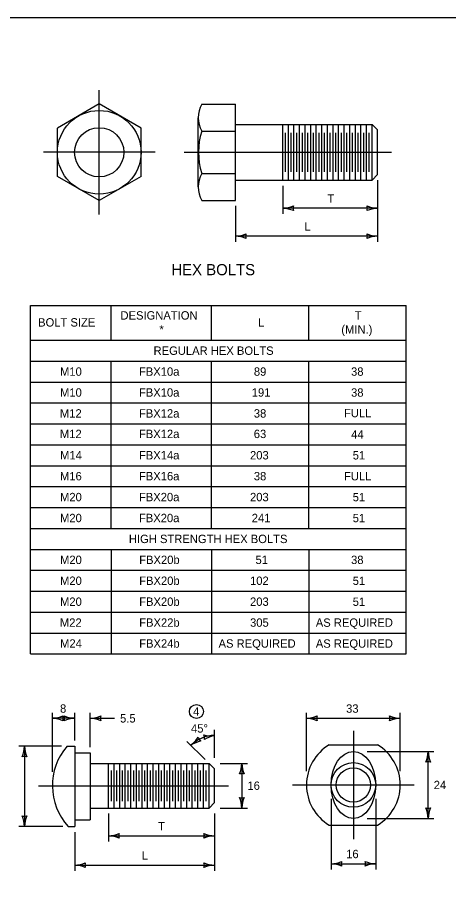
# Model space of a CAD drawing. Extents: x 49991.4 to 50021, y 49987.6 to 50011.4.
# Drawn here: x 50008.65 to 50011.74, y 49992.68 to 49999 of the extents above; entities that cross this region are included whole.
import ezdxf

# ---------------------------------------------------------------- set-up
doc = ezdxf.new("R2010")
doc.units = 0
for name, color, linetype in [('Level 1', 7, 'Continuous'), ('Level 2', 7, 'Continuous'), ('Level 3', 7, 'Continuous'), ('Level 4', 7, 'Continuous'), ('Level 5', 7, 'Continuous')]:
    doc.layers.add(name, color=color, linetype=linetype)

msp = doc.modelspace()

# ---------------------------------------------------------------- linework, layer by layer
at = {"layer": 'Level 1'}
for p, q in [((50009.2322, 49998.3799), (50008.9322, 49998.2067)), ((50009.5322, 49998.2067), (50009.2322, 49998.3799)), ((50009.9665, 49998.3782), (50010.2082, 49998.3782)), ((50010.2082, 49997.6887), (50010.2082, 49998.3782)), ((50009.9412, 49997.7862), (50009.9412, 49998.2808)), ((50008.9322, 49997.8602), (50008.9322, 49998.2067)), ((50009.5322, 49997.8602), (50009.5322, 49998.2067)), ((50010.2082, 49998.2335), (50011.1882, 49998.2335)), ((50010.5482, 49997.8335), (50010.5482, 49998.2335)), ((50010.5882, 49997.8335), (50010.5882, 49998.2335)), ((50010.6282, 49997.8335), (50010.6282, 49998.2335)), ((50010.6682, 49997.8335), (50010.6682, 49998.2335)), ((50010.7082, 49997.8335), (50010.7082, 49998.2335)), ((50010.7482, 49997.8335), (50010.7482, 49998.2335)), ((50010.7882, 49997.8335), (50010.7882, 49998.2335)), ((50010.8282, 49997.8335), (50010.8282, 49998.2335)), ((50010.8682, 49997.8335), (50010.8682, 49998.2335)), ((50010.9082, 49997.8335), (50010.9082, 49998.2335)), ((50010.9482, 49997.8335), (50010.9482, 49998.2335)), ((50010.9882, 49997.8335), (50010.9882, 49998.2335)), ((50011.0282, 49997.8335), (50011.0282, 49998.2335)), ((50011.0682, 49997.8335), (50011.0682, 49998.2335)), ((50011.1082, 49997.8335), (50011.1082, 49998.2335)), ((50011.1482, 49997.8335), (50011.1482, 49998.2335)), ((50011.1882, 49997.8335), (50011.1882, 49998.2335)), ((50011.1882, 49998.2335), (50011.2282, 49998.1935)), ((50009.9665, 49998.1852), (50010.2082, 49998.1852)), ((50010.5682, 49997.8935), (50010.5682, 49998.1735)), ((50010.6082, 49997.8935), (50010.6082, 49998.1735)), ((50010.6482, 49997.8935), (50010.6482, 49998.1735)), ((50010.6882, 49997.8935), (50010.6882, 49998.1735)), ((50010.7282, 49997.8935), (50010.7282, 49998.1735)), ((50010.7682, 49997.8935), (50010.7682, 49998.1735)), ((50010.8082, 49997.8935), (50010.8082, 49998.1735)), ((50010.8482, 49997.8935), (50010.8482, 49998.1735)), ((50010.8882, 49997.8935), (50010.8882, 49998.1735)), ((50010.9282, 49997.8935), (50010.9282, 49998.1735)), ((50010.9682, 49997.8935), (50010.9682, 49998.1735)), ((50011.0082, 49997.8935), (50011.0082, 49998.1735)), ((50011.0482, 49997.8935), (50011.0482, 49998.1735)), ((50011.0882, 49997.8935), (50011.0882, 49998.1735)), ((50011.1282, 49997.8935), (50011.1282, 49998.1735)), ((50011.1682, 49997.8935), (50011.1682, 49998.1735)), ((50011.2282, 49997.8735), (50011.2282, 49998.1935)), ((50009.2322, 49997.687), (50008.9322, 49997.8602)), ((50009.5322, 49997.8602), (50009.2322, 49997.687)), ((50009.9665, 49997.8817), (50010.2082, 49997.8817)), ((50010.2082, 49997.8335), (50011.1882, 49997.8335)), ((50011.1882, 49997.8335), (50011.2282, 49997.8735)), ((50009.9665, 49997.6887), (50010.2082, 49997.6887)), ((50010.881, 49993.7844), (50011.2271, 49993.7844)), ((50009.0016, 49993.7743), (50009.0562, 49993.7743)), ((50009.0562, 49993.7743), (50009.0562, 49993.1983)), ((50009.0562, 49993.7263), (50009.1682, 49993.7263)), ((50009.1682, 49993.7263), (50009.1682, 49993.2463)), ((50009.1682, 49993.6512), (50010.0192, 49993.6512)), ((50009.2992, 49993.3312), (50009.2992, 49993.6512)), ((50009.3192, 49993.3812), (50009.3192, 49993.6012)), ((50009.3392, 49993.3312), (50009.3392, 49993.6512)), ((50009.3592, 49993.3812), (50009.3592, 49993.6012)), ((50009.3792, 49993.3312), (50009.3792, 49993.6512)), ((50009.3992, 49993.3812), (50009.3992, 49993.6012)), ((50009.4192, 49993.3312), (50009.4192, 49993.6512)), ((50009.4392, 49993.3812), (50009.4392, 49993.6012)), ((50009.4592, 49993.3312), (50009.4592, 49993.6512)), ((50009.4792, 49993.3812), (50009.4792, 49993.6012)), ((50009.4992, 49993.3312), (50009.4992, 49993.6512)), ((50009.5192, 49993.3812), (50009.5192, 49993.6012)), ((50009.5392, 49993.3312), (50009.5392, 49993.6512)), ((50009.5592, 49993.3812), (50009.5592, 49993.6012)), ((50009.5792, 49993.3312), (50009.5792, 49993.6512)), ((50009.5992, 49993.3812), (50009.5992, 49993.6012)), ((50009.6192, 49993.3312), (50009.6192, 49993.6512)), ((50009.6392, 49993.3812), (50009.6392, 49993.6012)), ((50009.6592, 49993.3312), (50009.6592, 49993.6512)), ((50009.6792, 49993.3812), (50009.6792, 49993.6012)), ((50009.6992, 49993.3312), (50009.6992, 49993.6512)), ((50009.7192, 49993.3812), (50009.7192, 49993.6012)), ((50009.7392, 49993.3312), (50009.7392, 49993.6512)), ((50009.7592, 49993.3812), (50009.7592, 49993.6012)), ((50009.7792, 49993.3312), (50009.7792, 49993.6512)), ((50009.7992, 49993.3812), (50009.7992, 49993.6012)), ((50009.8192, 49993.3312), (50009.8192, 49993.6512)), ((50009.8392, 49993.3812), (50009.8392, 49993.6012)), ((50009.8592, 49993.3312), (50009.8592, 49993.6512)), ((50009.8792, 49993.3812), (50009.8792, 49993.6012)), ((50009.8992, 49993.3312), (50009.8992, 49993.6512)), ((50009.9192, 49993.3812), (50009.9192, 49993.6012)), ((50009.9392, 49993.3312), (50009.9392, 49993.6512)), ((50009.9592, 49993.3812), (50009.9592, 49993.6012)), ((50009.9792, 49993.3312), (50009.9792, 49993.6512)), ((50009.9992, 49993.3812), (50009.9992, 49993.6012)), ((50010.0192, 49993.3312), (50010.0192, 49993.6512)), ((50010.0192, 49993.6512), (50010.0592, 49993.6112)), ((50010.0592, 49993.3712), (50010.0592, 49993.6112)), ((50010.0192, 49993.3312), (50010.0592, 49993.3712)), ((50009.1682, 49993.3312), (50010.0192, 49993.3312)), ((50009.0562, 49993.2463), (50009.1682, 49993.2463)), ((50009.0104, 49993.1983), (50009.0562, 49993.1983)), ((50010.881, 49993.2084), (50011.2271, 49993.2084))]:
    msp.add_line(p, q, dxfattribs=at)
msp.add_lwpolyline([(49999.3835, 49998.9992), (50016.7501, 49998.9992), (50016.7501, 49987.7988), (49999.3835, 49987.7988)], close=True, dxfattribs=at)
for centre, radius in [((50009.2322, 49998.0335), 0.3), ((50011.0541, 49993.4964), 0.16), ((50011.0541, 49993.4964), 0.1225)]:
    msp.add_circle(centre, radius, dxfattribs=at)
for centre, radius, start, end in [((50010.1375, 49998.2817), 0.1963, 150.55282, 209.44718), ((50010.4667, 49998.0335), 0.5227, 163.12246, 196.87789), ((50010.1375, 49997.7852), 0.1963, 150.55289, 209.4483), ((50011.0541, 49993.4964), 0.336, 121.00272, 238.99728), ((50011.0541, 49993.4964), 0.336, 301.00272, 58.99728), ((50009.329, 49993.4912), 0.4328, 139.14882, 222.59192)]:
    msp.add_arc(centre, radius, start, end, dxfattribs=at)
msp.add_ellipse((50011.0541, 49993.4964), major_axis=(0, 0.24), ratio=0.666667, dxfattribs=at)
at = {"layer": 'Level 2'}
for p, q in [((50008.7404, 49996.936), (50011.4317, 49996.936)), ((50008.7404, 49994.436), (50008.7404, 49996.936)), ((50009.317, 49996.686), (50009.317, 49996.936)), ((50010.037, 49996.686), (50010.037, 49996.936)), ((50010.7344, 49996.686), (50010.7344, 49996.936)), ((50011.4317, 49994.436), (50011.4317, 49996.936)), ((50008.7404, 49996.686), (50011.4317, 49996.686)), ((50008.7404, 49996.536), (50011.4317, 49996.536)), ((50009.317, 49995.336), (50009.317, 49996.536)), ((50010.037, 49995.336), (50010.037, 49996.536)), ((50010.7344, 49995.336), (50010.7344, 49996.536)), ((50008.7404, 49996.386), (50011.4317, 49996.386)), ((50008.7404, 49996.236), (50011.4317, 49996.236)), ((50008.7404, 49996.086), (50011.4317, 49996.086)), ((50008.7404, 49995.936), (50011.4317, 49995.936)), ((50008.7404, 49995.786), (50011.4317, 49995.786)), ((50008.7404, 49995.636), (50011.4317, 49995.636)), ((50008.7404, 49995.486), (50011.4317, 49995.486)), ((50008.7404, 49995.336), (50011.4317, 49995.336)), ((50008.7404, 49995.186), (50011.4317, 49995.186)), ((50009.317, 49995.186), (50009.317, 49994.436)), ((50010.037, 49995.186), (50010.037, 49994.436)), ((50010.7344, 49995.186), (50010.7344, 49994.436)), ((50008.7404, 49995.036), (50011.4317, 49995.036)), ((50008.7404, 49994.886), (50011.4317, 49994.886)), ((50008.7404, 49994.736), (50011.4317, 49994.736)), ((50008.7404, 49994.586), (50011.4317, 49994.586)), ((50008.7404, 49994.436), (50011.4317, 49994.436))]:
    msp.add_line(p, q, dxfattribs=at)
msp.add_circle((50009.9289, 49994.0231), 0.05, dxfattribs=at)
at = {"layer": 'Level 3'}
for p, q in [((50011.2282, 49997.8335), (50011.2282, 49997.3919)), ((50010.5482, 49997.7935), (50010.5482, 49997.5919)), ((50010.2082, 49997.6487), (50010.2082, 49997.3919)), ((50011.2282, 49997.6319), (50010.5482, 49997.6319)), ((50011.2282, 49997.4319), (50010.2082, 49997.4319)), ((50008.8962, 49993.5912), (50008.8962, 49994.0143)), ((50009.0562, 49993.9743), (50008.8962, 49993.9743)), ((50009.0562, 49993.8143), (50009.0562, 49994.0143)), ((50009.1682, 49993.7663), (50009.1682, 49994.0143)), ((50009.1682, 49993.9743), (50009.3416, 49993.9743)), ((50010.7181, 49993.5964), (50010.7181, 49994.0143)), ((50010.7181, 49993.9743), (50011.3901, 49993.9743)), ((50011.3901, 49993.5964), (50011.3901, 49994.0143)), ((50010.0592, 49993.6912), (50010.0592, 49993.8912)), ((50009.991, 49993.6795), (50009.8612, 49993.8092)), ((50008.9616, 49993.7743), (50008.6562, 49993.7743)), ((50008.6962, 49993.7743), (50008.6962, 49993.1983)), ((50011.1541, 49993.7364), (50011.6301, 49993.7364)), ((50011.5901, 49993.2564), (50011.5901, 49993.7364)), ((50010.0992, 49993.6512), (50010.2948, 49993.6512)), ((50010.2548, 49993.6512), (50010.2548, 49993.3312)), ((50010.8941, 49993.3964), (50010.8941, 49992.8913)), ((50011.2141, 49993.3964), (50011.2141, 49992.8913)), ((50009.2992, 49993.2912), (50009.2992, 49993.0912)), ((50010.0592, 49993.2912), (50010.0592, 49992.8812)), ((50010.0992, 49993.3312), (50010.2948, 49993.3312)), ((50011.1541, 49993.2564), (50011.6301, 49993.2564)), ((50008.9704, 49993.1983), (50008.6562, 49993.1983)), ((50009.0562, 49993.1583), (50009.0562, 49992.8812)), ((50009.2992, 49993.1312), (50010.0592, 49993.1312)), ((50009.0562, 49992.9212), (50010.0592, 49992.9212)), ((50010.8941, 49992.9313), (50011.2141, 49992.9313))]:
    msp.add_line(p, q, dxfattribs=at)
for centre, radius, start, end in [((50010.5367, 49997.8646), 0.233, 272.82731, 292.07716), ((50010.6764, 49997.6319), 0.0548, 162.13882, 197.86118), ((50011.2373, 49997.854), 0.2223, 247.45601, 267.63952), ((50011.1, 49997.6319), 0.0548, 342.13882, 17.86118), ((50010.539, 49997.4097), 0.2223, 67.45601, 87.63952), ((50011.2397, 49997.3992), 0.233, 92.82731, 112.07716), ((50010.1967, 49997.6646), 0.233, 272.82731, 292.07716), ((50010.3364, 49997.4319), 0.0548, 162.13882, 197.86118), ((50011.2373, 49997.654), 0.2223, 247.45601, 267.63952), ((50011.1, 49997.4319), 0.0548, 342.13882, 17.86118), ((50010.199, 49997.2097), 0.2223, 67.45601, 87.63952), ((50011.2397, 49997.1992), 0.233, 92.82731, 112.07716), ((50008.8847, 49994.207), 0.233, 272.82731, 292.07716), ((50008.887, 49993.7522), 0.2223, 67.45601, 87.63952), ((50009.0244, 49993.9743), 0.0548, 162.13882, 197.86118), ((50009.0654, 49994.1964), 0.2223, 247.45601, 267.63952), ((50008.928, 49993.9743), 0.0548, 342.13882, 17.86118), ((50009.0677, 49993.7416), 0.233, 92.82731, 112.07716), ((50009.1567, 49994.207), 0.233, 272.82731, 292.07716), ((50009.159, 49993.7522), 0.2223, 67.45601, 87.63952), ((50009.2964, 49993.9743), 0.0548, 162.13882, 197.86118), ((50010.7089, 49994.1964), 0.2223, 272.36047, 292.54398), ((50010.7066, 49993.7416), 0.233, 67.92283, 87.17268), ((50010.8463, 49993.9743), 0.0548, 162.13881, 197.86118), ((50011.2619, 49993.9743), 0.0548, 342.13881, 17.86118), ((50011.4016, 49994.207), 0.233, 247.92283, 267.17268), ((50011.3992, 49993.7522), 0.2223, 92.36047, 112.54398), ((50010.0592, 49993.6112), 0.24, 90, 135.00008), ((50010.0324, 49994.0719), 0.2223, 256.74849, 276.932), ((50009.9327, 49993.8305), 0.0548, 351.4313, 27.15366), ((50010.1082, 49993.6234), 0.233, 102.11979, 121.36964), ((50009.7438, 49993.9627), 0.233, 308.71738, 327.96723), ((50010.0123, 49993.5956), 0.2223, 103.34608, 123.52958), ((50009.9934, 49993.8561), 0.0548, 198.02888, 233.75125), ((50008.4741, 49993.7835), 0.2223, 337.45596, 357.63947), ((50008.9289, 49993.7858), 0.233, 182.82726, 202.07711), ((50011.3679, 49993.7456), 0.2223, 337.45596, 357.63947), ((50011.8228, 49993.7479), 0.233, 182.82726, 202.07711), ((50008.6962, 49993.6461), 0.0548, 72.13877, 107.86113), ((50011.5901, 49993.6082), 0.0548, 72.13877, 107.86113), ((50010.0326, 49993.6604), 0.2223, 337.45596, 357.63947), ((50010.4875, 49993.6627), 0.233, 182.82726, 202.07711), ((50010.2548, 49993.523), 0.0548, 72.13877, 107.86113), ((50010.2548, 49993.4594), 0.0548, 252.13877, 287.86113), ((50010.0221, 49993.3197), 0.233, 2.82726, 22.07711), ((50010.4769, 49993.3221), 0.2223, 157.45596, 177.63947), ((50008.6962, 49993.3265), 0.0548, 252.13877, 287.86113), ((50008.4635, 49993.1868), 0.233, 2.82726, 22.07711), ((50008.9183, 49993.1891), 0.2223, 157.45596, 177.63947), ((50011.5901, 49993.3846), 0.0548, 252.13877, 287.86113), ((50011.3574, 49993.2449), 0.233, 2.82726, 22.07711), ((50011.8122, 49993.2473), 0.2223, 157.45596, 177.63947), ((50009.2877, 49993.3639), 0.233, 272.82731, 292.07716), ((50009.4275, 49993.1312), 0.0548, 162.13882, 197.86118), ((50010.0684, 49993.3534), 0.2223, 247.45601, 267.63952), ((50009.931, 49993.1312), 0.0548, 342.13882, 17.86118), ((50009.2901, 49992.9091), 0.2223, 67.45601, 87.63952), ((50010.0707, 49992.8985), 0.233, 92.82731, 112.07716), ((50009.0447, 49993.1539), 0.233, 272.82731, 292.07716), ((50009.047, 49992.6991), 0.2223, 67.45601, 87.63952), ((50009.1844, 49992.9212), 0.0548, 162.13882, 197.86118), ((50010.0684, 49993.1434), 0.2223, 247.45601, 267.63952), ((50009.931, 49992.9212), 0.0548, 342.13882, 17.86118), ((50010.0707, 49992.6885), 0.233, 92.82731, 112.07716), ((50010.8849, 49993.1535), 0.2223, 272.36047, 292.54398), ((50010.8826, 49992.6986), 0.233, 67.92283, 87.17268), ((50011.0223, 49992.9313), 0.0548, 162.13881, 197.86118), ((50011.0859, 49992.9313), 0.0548, 342.13881, 17.86118), ((50011.2256, 49993.1641), 0.233, 247.92283, 267.17268), ((50011.2232, 49992.7092), 0.2223, 92.36047, 112.54398)]:
    msp.add_arc(centre, radius, start, end, dxfattribs=at)
at = {"layer": 'Level 4'}
msp.add_circle((50009.2322, 49998.0335), 0.1765, dxfattribs=at)
at = {"layer": 'Level 5'}
for p, q in [((50009.2322, 49997.587), (50009.2322, 49998.4799)), ((50009.6322, 49998.0335), (50008.8322, 49998.0335)), ((50009.8412, 49998.0335), (50011.3282, 49998.0335)), ((50011.0541, 49993.8844), (50011.0541, 49993.1084)), ((50008.7962, 49993.4912), (50010.1592, 49993.4912)), ((50010.6181, 49993.4964), (50011.4901, 49993.4964))]:
    msp.add_line(p, q, dxfattribs=at)

# ---------------------------------------------------------------- texts
at = {"layer": 'Level 2'}
for s, height, p in [('T', 0.06, (50010.8685, 49997.6719)), ('L', 0.06, (50010.7037, 49997.4719)), ('HEX BOLTS', 0.08, (50009.7492, 49997.1519)), ('DESIGNATION', 0.06, (50009.3843, 49996.8337)), ('T', 0.06, (50011.0634, 49996.8337)), ('BOLT SIZE', 0.06, (50008.7939, 49996.7838)), ('L', 0.06, (50010.3711, 49996.7837)), ('*', 0.06, (50009.6635, 49996.7337)), ('(MIN.)', 0.06, (50010.9675, 49996.7337)), ('REGULAR HEX BOLTS', 0.06, (50009.6216, 49996.581)), ('M10', 0.06, (50008.9511, 49996.431)), ('FBX10a', 0.06, (50009.517, 49996.431)), ('89', 0.06, (50010.3408, 49996.431)), ('38', 0.06, (50011.0375, 49996.431)), ('M10', 0.06, (50008.9511, 49996.281)), ('FBX10a', 0.06, (50009.517, 49996.281)), ('191', 0.06, (50010.3254, 49996.281)), ('38', 0.06, (50011.0375, 49996.2807)), ('M12', 0.06, (50008.9502, 49996.131)), ('FBX12a', 0.06, (50009.517, 49996.131)), ('38', 0.06, (50010.3404, 49996.131)), ('FULL', 0.06, (50010.9869, 49996.1337)), ('M12', 0.06, (50008.9502, 49995.984)), ('FBX12a', 0.06, (50009.517, 49995.984)), ('63', 0.06, (50010.3402, 49995.984)), ('44', 0.06, (50011.0385, 49995.9807)), ('M14', 0.06, (50008.9514, 49995.831)), ('FBX14a', 0.06, (50009.517, 49995.831)), ('203', 0.06, (50010.3132, 49995.831)), ('51', 0.06, (50011.0495, 49995.8307)), ('M16', 0.06, (50008.9509, 49995.6809)), ('FBX16a', 0.06, (50009.517, 49995.681)), ('38', 0.06, (50010.3404, 49995.681)), ('FULL', 0.06, (50010.9869, 49995.6807)), ('M20', 0.06, (50008.9511, 49995.5309)), ('FBX20a', 0.06, (50009.517, 49995.531)), ('203', 0.06, (50010.3132, 49995.531)), ('51', 0.06, (50011.0495, 49995.5307)), ('M20', 0.06, (50008.9511, 49995.3809)), ('FBX20a', 0.06, (50009.517, 49995.381)), ('241', 0.06, (50010.3254, 49995.381)), ('51', 0.06, (50011.0495, 49995.3807)), ('HIGH STRENGTH HEX BOLTS', 0.06, (50009.4448, 49995.231)), ('M20', 0.06, (50008.9511, 49995.0809)), ('FBX20b', 0.06, (50009.5187, 49995.081)), ('51', 0.06, (50010.3524, 49995.081)), ('38', 0.06, (50011.0375, 49995.0807)), ('M20', 0.06, (50008.9511, 49994.9309)), ('FBX20b', 0.06, (50009.5187, 49994.931)), ('102', 0.06, (50010.3133, 49994.931)), ('51', 0.06, (50011.0495, 49994.9307)), ('M20', 0.06, (50008.9511, 49994.7809)), ('FBX20b', 0.06, (50009.5187, 49994.781)), ('203', 0.06, (50010.3132, 49994.781)), ('51', 0.06, (50011.0495, 49994.7807)), ('M22', 0.06, (50008.9502, 49994.6309)), ('FBX22b', 0.06, (50009.5187, 49994.631)), ('305', 0.06, (50010.3135, 49994.631)), ('AS REQUIRED', 0.06, (50010.7847, 49994.6307)), ('M24', 0.06, (50008.9514, 49994.4809)), ('FBX24b', 0.06, (50009.5187, 49994.481)), ('AS REQUIRED', 0.06, (50010.0875, 49994.481)), ('AS REQUIRED', 0.06, (50010.7847, 49994.4807)), ('8', 0.06, (50008.9512, 49994.0143)), ('4', 0.06, (50009.9049, 49993.9931)), ('33', 0.06, (50011.0019, 49994.0143)), ('5.5', 0.06, (50009.3816, 49993.9443)), ('45°', 0.06, (50009.89, 49993.8721)), ('24', 0.06, (50011.6301, 49993.4664)), ('16', 0.06, (50010.2948, 49993.4612)), ('T', 0.06, (50009.6532, 49993.1712)), ('L', 0.06, (50009.5365, 49992.9612)), ('16', 0.06, (50011.0026, 49992.9713))]:
    msp.add_text(s, height=height, dxfattribs=at).set_placement(p)

doc.saveas('drawing.dxf')
